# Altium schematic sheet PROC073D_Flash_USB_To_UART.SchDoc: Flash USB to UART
size 431 x 279 mm; Date: Not shown in title block; ApprovedBy: Not shown in title block; CheckedBy: Not shown in title block; Author: Not shown in title block; CompanyName: Not shown in title block; DrawnBy: Charles F. Oladimeji; Engineer: Not shown in title block; Organization: Not shown in title block; Address1: Not shown in title block; Address2: Not shown in title block; Address3: Not shown in title block; Address4: Not shown in title block; DocumentNumber: 9; Revision: Use project parameter SCH_Rev; SheetNumber: 9; SheetTotal: 13; PageSetup: Record=PageOptions¦CenterHorizontal=True¦CenterVertical=True¦PrintScale=1.00¦XCorrection=1.00¦YCorrection=1.00¦PrintKind=0¦BorderSize=5000000¦LeftOffset=0¦BottomOffset=0¦Orientation=2¦PaperLength=1000¦PaperWidth=1000¦Scale=100¦PaperSource=15¦PrintQuality=600¦MediaType=1¦DitherType=10¦PaperKind=Letter¦PrintScaleMode=1
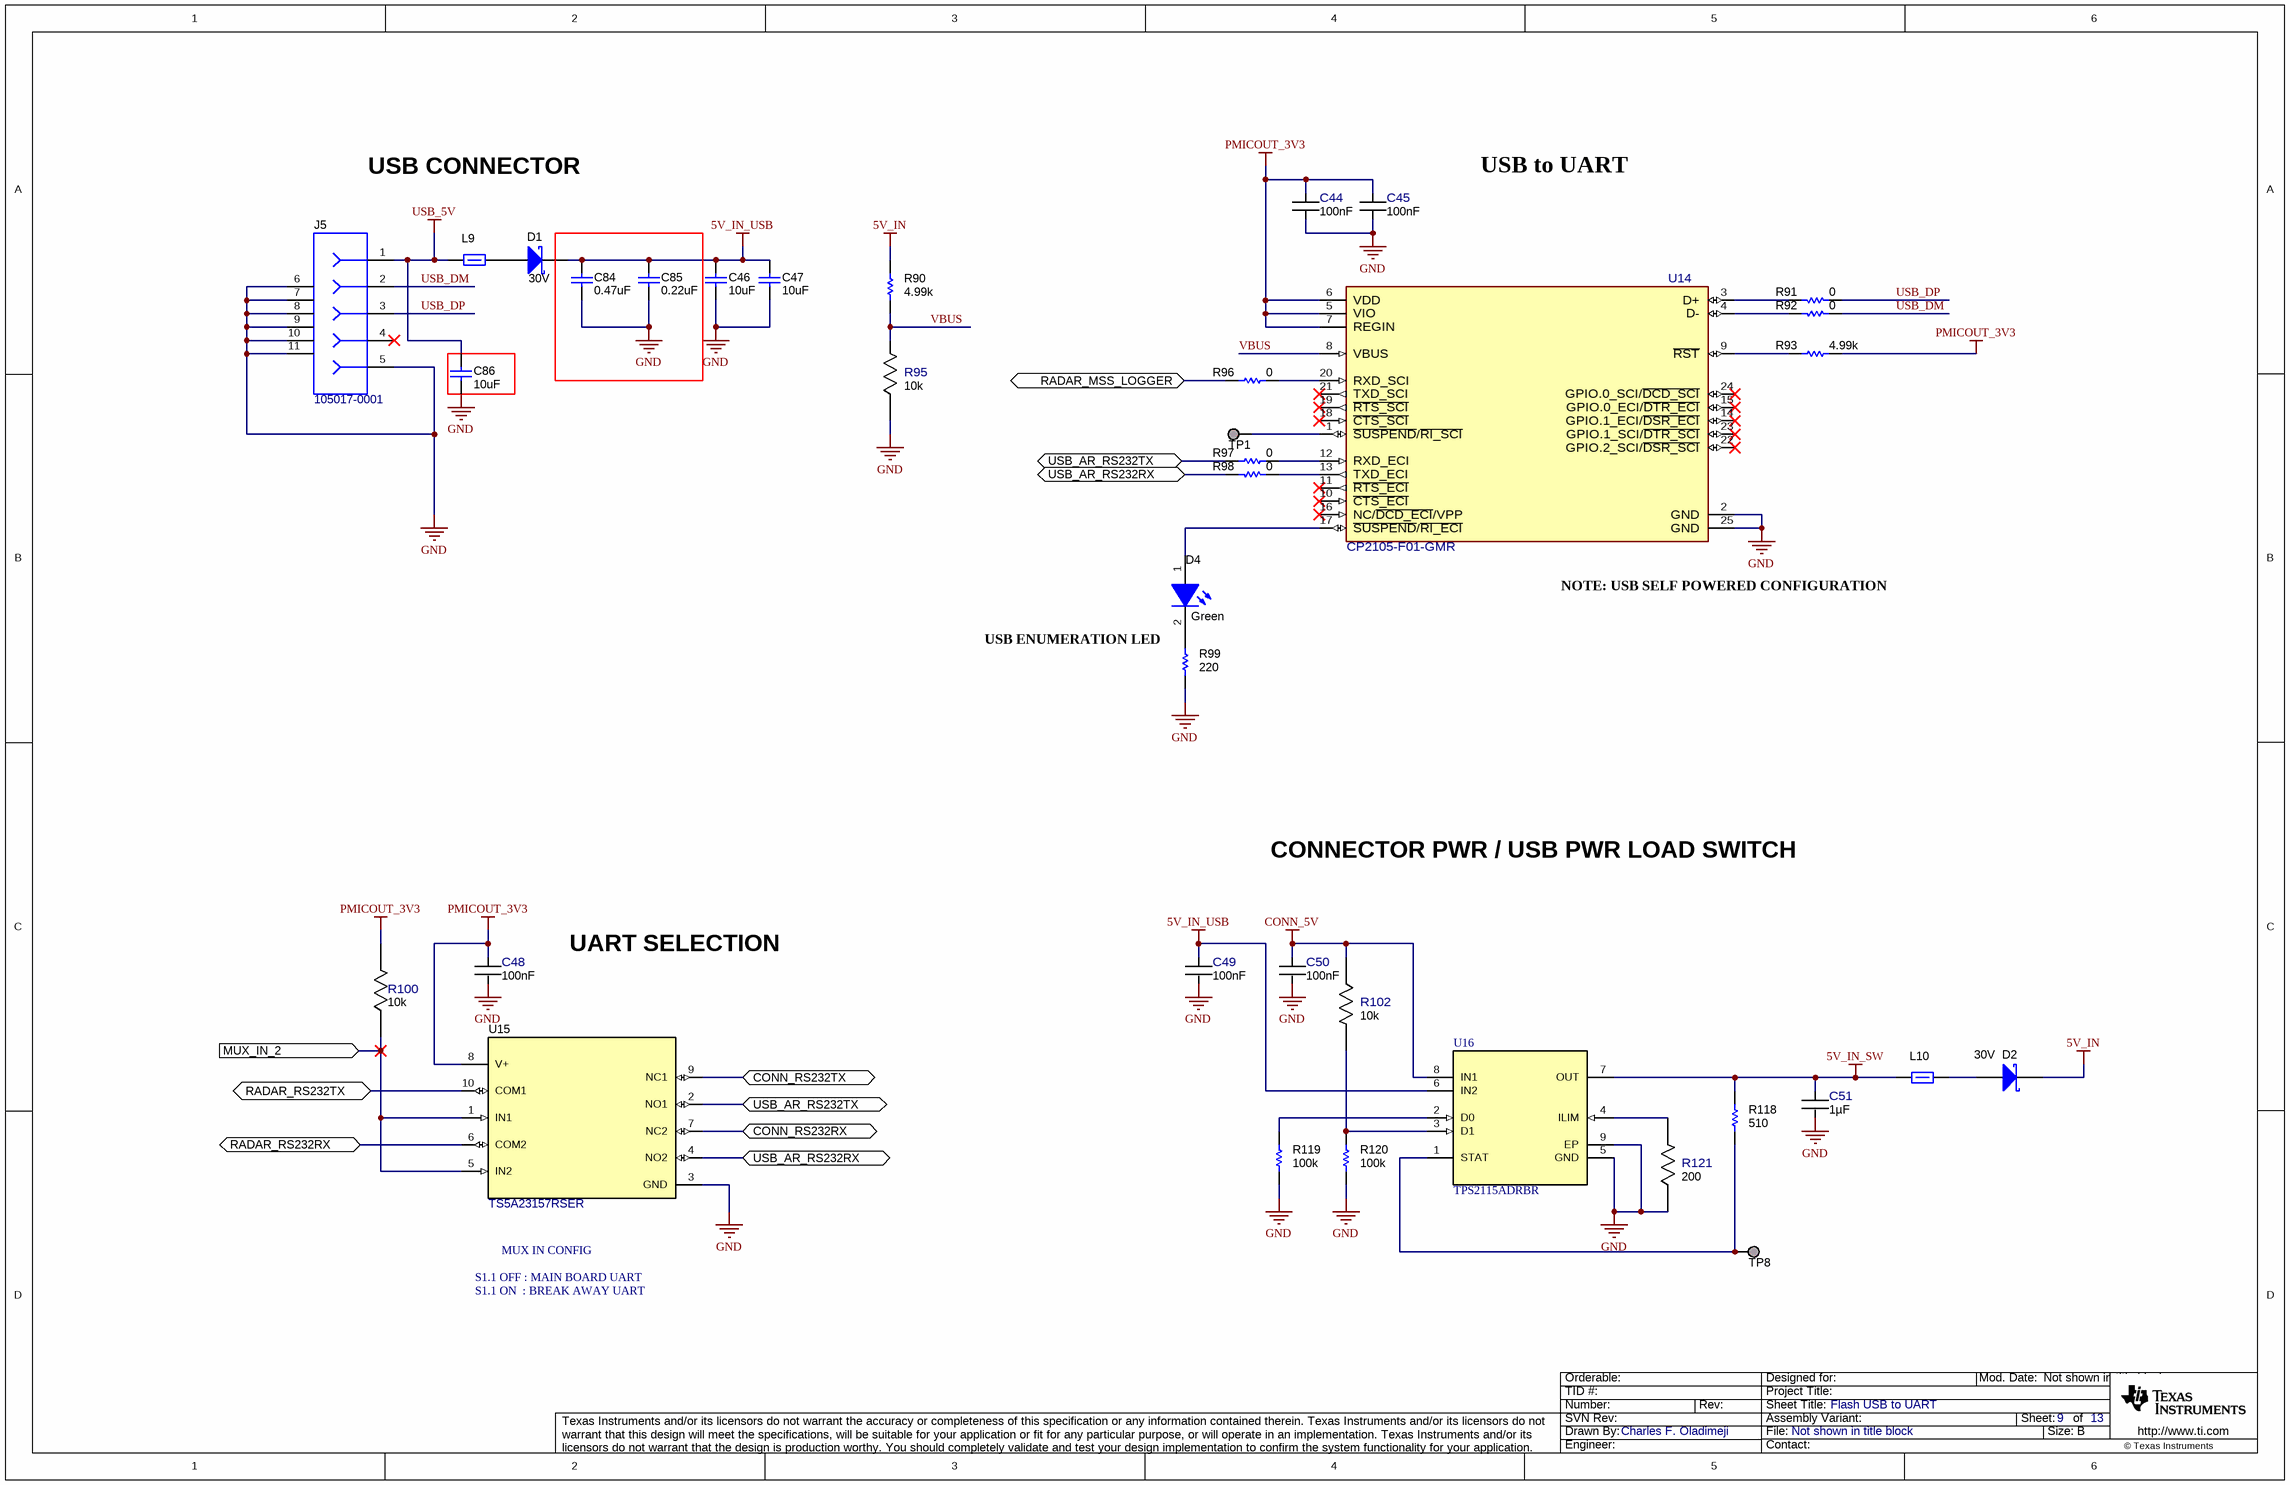
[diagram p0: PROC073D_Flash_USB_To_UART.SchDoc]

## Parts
C44  Cap_F: 100nF  [FP-GRM033R6YA104KE14D_0201 (0603 Metric)-IPC_C]  (hidden comment: GRM033R6YA104KE14D)
C45  Cap_F: 100nF  [FP-GRM033R6YA104KE14D_0201 (0603 Metric)-IPC_C]  (hidden comment: GRM033R6YA104KE14D)
C46  value 10uF  [0402_070]  (hidden comment: CL05A106MP5NUNC)
C47  value 10uF  [0402_070]  (hidden comment: CL05A106MP5NUNC)
C48  Cap_F: 100nF  [FP-GRM033R6YA104KE14D_0201 (0603 Metric)-IPC_C]  (hidden comment: GRM033R6YA104KE14D)
C49  Cap_F: 100nF  [FP-GRM033R6YA104KE14D_0201 (0603 Metric)-IPC_C]  (hidden comment: GRM033R6YA104KE14D)
C50  Cap_F: 100nF  [FP-GRM033R6YA104KE14D_0201 (0603 Metric)-IPC_C]  (hidden comment: GRM033R6YA104KE14D)
C51  Cap_F: 1µF  [FP-CL03A105MO3NRNH_0201-IPC_C]  (hidden comment: CL03A105MO3NRNH)
C84  ValueDisplayed: 0.47uF  [0402L]  (hidden comment: GCM155C71A474KE36D)
C85  ValueDisplayed: 0.22uF  [0402S]  (hidden comment: LMK105B7224KVHF)
C86  ValueDisplayed: 10uF  [0603S]  (hidden comment: GRT188R61A106KE13D)
D1  value 30V  [DSN2_0603]  (hidden comment: NSR20F30NXT5G)
D2  value 30V  [DSN2_0603]  (hidden comment: NSR20F30NXT5G)
D4  Color: Green  [APHHS1005_Green]  (hidden comment: APHHS1005CGCK)
J5  105017-0001  [CONN_105017-0001]
L9  BLM15PD300SZ1D  [0402L]  (value not drawn)
L10  BLM15PD300SZ1D  [0402L]  (value not drawn)
R90  value 4.99k  [0201L]  (hidden comment: RC0201FR-074K99L)
R91  Res_ohm: 0  [FP-RC0201JR-070RL_0201 (0603 Metric)-MFG]  (hidden comment: RC0201JR-070RL)
R92  Res_ohm: 0  [FP-RC0201JR-070RL_0201 (0603 Metric)-MFG]  (hidden comment: RC0201JR-070RL)
R93  value 4.99k  [0201L]  (hidden comment: RC0201FR-074K99L)
R95  Res_ohm: 10k  [FP-RR0306P-103-D_0201-IPC_C]  (hidden comment: RR0306P-103-D)
R96  Res_ohm: 0  [FP-RC0201JR-070RL_0201 (0603 Metric)-MFG]  (hidden comment: RC0201JR-070RL)
R97  Res_ohm: 0  [FP-RC0201JR-070RL_0201 (0603 Metric)-MFG]  (hidden comment: RC0201JR-070RL)
R98  Res_ohm: 0  [FP-RC0201JR-070RL_0201 (0603 Metric)-MFG]  (hidden comment: RC0201JR-070RL)
R99  value 220  [0201L]  (hidden comment: RC0201JR-07220RL)
R100  Res_ohm: 10k  [FP-RR0306P-103-D_0201-IPC_C]  (hidden comment: RR0306P-103-D)
R102  Res_ohm: 10k  [FP-RR0306P-103-D_0201-IPC_C]  (hidden comment: RR0306P-103-D)
R118  value 510  [0201L]  (hidden comment: RC0201JR-07510RL)
R119  value 100k  [0201L]  (hidden comment: CRCW0201100KFKED)
R120  value 100k  [0201L]  (hidden comment: CRCW0201100KFKED)
R121  Res_ohm: 200  [FP-CRCW0402200RFKEDHP_0402-IPC_C]  (hidden comment: CRCW0402200RFKEDHP)
TP1  TESTPOINT  [TP_25MIL-SMT]  (value not drawn)  (no BOM)
TP8  TESTPOINT  [TP_25MIL-SMT]  (value not drawn)  (no BOM)
U14  CP2105-F01-GMR  [FP-CP2105-F01-GMR_QFN24-EP-IPC_A]
U15  TS5A23157RSER  [RSE0010A]
U16  TPS2115ADRBR  [DRB0008B]

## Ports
CONN_RS232RX (bidir), CONN_RS232TX (bidir), MUX_IN_2 (in), RADAR_MSS_LOGGER (bidir), RADAR_RS232RX (bidir), RADAR_RS232TX (bidir), USB_AR_RS232RX (bidir), USB_AR_RS232TX (bidir)

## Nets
5V_IN: D2.1(K) R90.1
5V_IN_SW: C51.1 L10.1 R118.1 U16.7(OUT)
5V_IN_USB: C46.2 C47.1 C49.1 C84.1 C85.1 D1.1(K) U16.6(IN2)
CONN_5V: C50.1 R102.1 U16.8(IN1)
GND: C44.1 C45.1 C46.1 C47.2 C48.2 C49.2 C50.2 C51.2 C84.2 C85.2 C86.1 J5.5 J5.6 J5.7 J5.8 J5.9 J5.10 J5.11 R95.1 R99.1 R119.2 R120.1 R121.1 U14.2(GND) U14.25(GND) U15.3(GND) U16.5(GND) U16.9(EP)
PMICOUT_3V3: C44.2 C45.2 C48.1 R93.1 R100.2 U14.5(VIO) U14.6(VDD) U14.7(REGIN) U15.8(V+)
USB_5V: C86.2 J5.1 L9.1
CONN_RS232RX: U15.7(NC2) ; port CONN_RS232RX
CONN_RS232TX: U15.9(NC1) ; port CONN_RS232TX
MUX_IN_2: R100.1 U15.1(IN1) U15.5(IN2) ; port MUX_IN_2
RADAR_MSS_LOGGER: R96.2 ; port RADAR_MSS_LOGGER
RADAR_RS232RX: U15.6(COM2) ; port RADAR_RS232RX
RADAR_RS232TX: U15.10(COM1) ; port RADAR_RS232TX
USB_AR_RS232RX: R98.1 U15.4(NO2) ; port USB_AR_RS232RX
USB_AR_RS232TX: R97.2 U15.2(NO1) ; port USB_AR_RS232TX
USB_DM: J5.2 R92.2
USB_DP: J5.3 R91.2
VBUS: R90.2 R95.2 U14.8(VBUS)
NetD1_2: D1.2(A) L9.2
NetD2_2: D2.2(A) L10.2
NetD4_1: D4.1(A) U14.17(~{SUSPEND}/~{RI_ECI})
NetD4_2: D4.2(K) R99.2
NetR91_1: R91.1 U14.3(D+)
NetR92_1: R92.1 U14.4(D-)
NetR93_2: R93.2 U14.9(~{RST})
NetR96_1: R96.1 U14.20(RXD_SCI)
NetR97_1: R97.1 U14.12(RXD_ECI)
NetR98_2: R98.2 U14.13(TXD_ECI)
NetR102_2: R102.2 R120.2 U16.3(D1)
NetR118_2: R118.2 TP8.1 U16.1(STAT)
NetR119_1: R119.1 U16.2(D0)
NetR121_2: R121.2 U16.4(ILIM)
NetTP1_1: TP1.1 U14.1(~{SUSPEND}/~{RI_SCI})

Not connected (* = marked no-connect by the designer): J5 4*; U14 10(~{CTS_ECI})* 11(~{RTS_ECI})* 14(GPIO.1_ECI/~{DSR_ECI})* 15(GPIO.0_ECI/~{DTR_ECI})* 16(NC/~{DCD_ECI}/VPP)* 18(~{CTS_SCI})* 19(~{RTS_SCI})* 21(TXD_SCI)* 22(GPIO.2_SCI/~{DSR_SCI})* 23(GPIO.1_SCI/~{DTR_SCI})* 24(GPIO.0_SCI/~{DCD_SCI})*

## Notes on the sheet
- USB CONNECTOR
- USB to UART
- (near U14) NOTE: USB SELF POWERED CONFIGURATION
- USB ENUMERATION LED
- CONNECTOR PWR / USB PWR LOAD SWITCH
- UART SELECTION
- S1.1 ON  : BREAK AWAY UART
- S1.1 OFF : MAIN BOARD UART
- MUX IN CONFIG

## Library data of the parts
C44 C45 C48-C50 = CMP-0086440-1: Cap Ceramic 0.1uF 35V X5R 10% Pad SMD 0201 85C T/R; Manufacturer: Murata Electronics North America; AEC Qualified: No; SizeZ_mm: 0.33mm; Symbol Name: SYM-GRM033R6YA104KE14D; TempCo: 15%
C46 C47 = CMP-0006339-4: CAP, CERM, 10 uF, 10 V, +/- 20%, X5R, 0402; Manufacturer: Samsung Electro-Mechanics; AEC Category: Q200; AEC Qualified: N; Cap_Case: 0402; Cap_F: 10µF; SizeArea_mm2: 0.5; SizeAreaWB_mm2: 3; SizeX_mm: 1; SizeZ_mm: 0.6; TaMax_C: 85°C; TaMin_C: -55°C; U/M: EA; Value1: Unknown; Value2: 10V
C51 = CMP-0086446-1: 1µF ±20% 16V Ceramic Capacitor X5R 0201; Manufacturer: Samsung Electro-Mechanics; AEC Qualified: No; SizeZ_mm: 0.39mm; Symbol Name: SYM-CL03A105MO3NRNH; TempCo: 15%
C84 = CMP-0064967-2: CAP, CERM, 0.47 uF, 10 V,+/- 10%, X7S, 0402; Manufacturer: MuRata; Polarized: N; Value: 0.47uF; U/M: EA; Cap_F: 470nF; Value1: Unknown; VDC_V: 10V; TaMin_C: -55°C; TaMax_C: 125°C; Cap_Case: 0402; SizeArea_mm2: 0.5; SizeAreaWB_mm2: 3; SizeX_mm: 1; SizeZ_mm: 0.6; AEC Category: Q200
C85 = CMP-0006262-2: CAP, CERM, 0.22 uF, 10 V, +/- 10%, X7R, 0402; Manufacturer: TDK; Polarized: N; Value: 0.22uF; U/M: EA; Cap_F: 220nF; Value1: Unknown; VDC_V: 10V; TempCo: X5R; TaMin_C: -55°C; TaMax_C: 85°C; Cap_Case: 0402; SizeArea_mm2: 0.5; SizeAreaWB_mm2: 3; SizeX_mm: 1; SizeZ_mm: 0.6; AEC Category: Q200
C86 = CMP-0007497-5: CAP, CERM, 10 uF, 10 V, +/- 10%, X5R, 0603; Manufacturer: MuRata; Polarized: N; Value: 10uF; U/M: EA; Cap_F: 10µF; Tolerance_%: 20%; Value1: Unknown; VDC_V: 10V; TempCo: X7R; TaMin_C: -55°C; TaMax_C: 125°C; Cap_Case: 0603; SizeArea_mm2: 1.28; SizeAreaWB_mm2: 4.68; SizeX_mm: 1.6; SizeY_mm: 0.8; SizeZ_mm: 1; AEC Category: Q200
D1 D2 = CMP-0028829-2: Diode, Schottky, 30 V, 2 A, 2-XFDFN; Manufacturer: ON Semiconductor; Value2: 0.48V; SizeY_mm: 0.8; TJmax_C: 150°C; Green_Lifecycle: Not Set; SizeAreaWB_mm2: 4.68; Value1: 2A; SizeArea_mm2: 1.28; Green_REACh: Incomplete; AEC Category: Q101; SizeZ_mm: 0.31; Vf_V: 480mV; AEC Qualified: N; SizeX_mm: 1.6
D4 = CMP-0067682-2: LED, Green, SMD; Manufacturer: Kingbright; Angle: 120.0; Power_TotalModule: 75mW; SizeZ_mm: 0.6; Vf_V: 2.1V; Vr_V: 5V; Io_A: 20mA; Ir_A: 10µA; SizeArea_mm2: 0.5; SizeAreaWB_mm2: 3.0; SizeX_mm: 1.0; Tjmax_C: 85°C; Value1: 0.075W
J5 = CMP-0055293-1: Connector, Receptacle, Micro-USB Type B, R/A, Bottom Mount SMT; Manufacturer: Molex; CNHeader: FALSE; CompType: USB; CT: TRUE; Gender: Female; Green_Lifecycle: Active; Green_REACh: Passed
L9 L10 = CMP-0078934-1: Inductor, Ferrite Bead, Ferrite, 2.2 A, 0.035 ohm, AEC-Q200 Grade 1, SMD; Manufacturer: MuRata; AEC Category: Q200; AEC Grade: 1; AEC Qualified: Y; DCR_ohm: 0.035; Imax_A: 2.2A; SizeArea_mm2: 0.5; SizeAreaWB_mm2: 3; SizeZ_mm: 0.6
R90 R93 = CMP-0027745-1: RES, 4.99 k, 1%, 0.05 W, 0201; Manufacturer: Yageo America; AEC Category: Q200; AEC Qualified: N; EIA_Code: E96; Power_W: 50mW; SizeArea_mm2: 0.18; SizeX_mm: 0.6; SizeY_mm: 0.3; SizeZ_mm: 0.26; TempCo: 200 ppm/C; U/M: EA; Value2: 0.05W; Value_Code: 4k99; VDC_V: 25V
R91 R92 R96-R98 = CMP-0086442-2: RES SMD 0 OHM JUMPER 1/20W 0201; Manufacturer: Yageo; AEC Qualified: No; Power_W: 50mW; SizeZ_mm: 0.26mm; TempCo: 200ppm/°C; Tolerance_%: 5%; VDC_V: 25V
R95 R100 R102 = CMP-0088002-1: 10 kOhms ±0.5% 0.05W, 1/20W Chip Resistor 0201 (0603 Metric)  Thin Film; Manufacturer: Susumu; AEC Qualified: No; Power_W: 50mW; SizeZ_mm: 0.26mm; Symbol Name: SYM-RR0306P-103-D; TempCo: 25ppm/°C; VDC_V: 15V
R99 = CMP-0027072-1: RES, 220, 5%, 0.05 W, 0201; Manufacturer: Yageo America; AEC Category: Q200; AEC Qualified: N; EIA_Code: E24; Power_W: 50mW; SizeArea_mm2: 0.18; SizeX_mm: 0.6; SizeY_mm: 0.3; SizeZ_mm: 0.26; TempCo: 200 ppm/C; U/M: EA; Value2: 0.05W; Value_Code: 220R; VDC_V: 25V
R118 = CMP-0027137-1: RES, 510, 5%, 0.05 W, 0201; Manufacturer: Yageo America; AEC Category: Q200; AEC Qualified: N; EIA_Code: E24; Power_W: 50mW; SizeArea_mm2: 0.18; SizeX_mm: 0.6; SizeY_mm: 0.3; SizeZ_mm: 0.26; TempCo: 200 ppm/C; U/M: EA; Value2: 0.05W; Value_Code: 510R; VDC_V: 25V
R119 R120 = CMP-0027261-3: RES, 100 k, 1%, 0.05 W, 0201; Manufacturer: Vishay-Dale; AEC Category: Q200; AEC Qualified: N; EIA_Code: E96; Power_W: 50mW; SizeArea_mm2: 0.18; SizeX_mm: 0.6; SizeY_mm: 0.3; SizeZ_mm: 0.26; TempCo: 100 ppm/C; Value2: 0.05W; VDC_V: 30V
R121 = CMP-0087183-1: RES SMD 200 OHM 1% 1/5W 0402; Manufacturer: Vishay Dale; AEC Grade: Grade 0; AEC Qualified: Yes; Power_W: 200mW; SizeZ_mm: 0.4mm; Symbol Name: SYM-CRCW0402200RFKEDHP; TempCo: 100ppm/°C; VDC_V: 50V
TP1 TP8 = CMP-0078143-3: TEST POINT.  No entry in BOM.
U14 = CMP-0087172-1: I/O Controller Interface IC USB to Dual UART bridge; Manufacturer: Silicon Labs; SizeZ_mm: 0.8mm
U15 = CMP-0074545-1: Dual 10-ohm SPDT Analog Switch, RSE0010A (UQFN-10); Alternate Manufacturer: Texas Instruments; CompType: IC; SizeArea_mm2: 3.0; SizeAreaWB_mm2: 7.5; SizeX_mm: 1.5; SizeY_mm: 2.0; SizeZ_mm: 0.6; U/M: EA
U16 = CMP-0043358-3: Dual In / Single Out Autoswitching Power Mux, 2.8 to 5.5 V, -40 to 85 degC, 8-pin SON (DRB), Green (RoHS & no Sb/Br); Manufacturer: Texas Instruments; AEC Category: Q200; AEC Qualified: N; CompType: IC; IN1, IN2 Input Voltage(Max)(V): 5.5; IN1, IN2 Input Voltage(Min)(V): 2.8; IN1 Output Current(Max)(A): 1.25; IN1 rDS(on)(Typ)(mOhm): 84; IN2 rDS(on)(Typ)(Ohms): 0.084; Number of Inputs: 2; SizeArea_mm2: 9.0; SizeAreaWB_mm2: 16.0; SizeX_mm: 3.0; SizeZ_mm: 1.0; SubFamily: Power Multiplexer (MUX)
